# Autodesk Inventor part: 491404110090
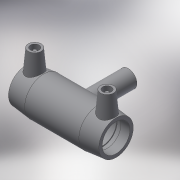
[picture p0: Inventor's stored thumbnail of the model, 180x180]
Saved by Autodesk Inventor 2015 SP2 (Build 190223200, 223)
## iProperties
Created: 2017-06
Part Number: 491404110090
Material: Generic
Description: PLASSON REDUCING TEE 110x90x110
Document SubType Name: Modeling
Designer: KIM
Mass: 57.3761 g
Surface Area: 241.06 cm^2
Volume: 57.3761 cm^3
Density: 1 g/cm^3
Appearance: Default
Author: KIM
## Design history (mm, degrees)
derived "491404.ipt"
feature "Solid1::491404.ipt"
tag "TaggingFeature1"
body "Solid1"
other parameters: "d0" = 326, "d2" = 143, "d3" = 71, "d4" = 65.2, "d5" = 128.7, "d6" = 104.5, "d8" = 168 deg, "d10" = 28.4, "d11" = 9.46667, "d13" = 326, "d14" = 17.6296, "d17" = 99, "d19" = 3.52592, "d20" = 168 deg, "d22" = 132.99, "d23" = 143, "d25" = 135 deg, "d26" = 228.2, "d29" = 81, "d30" = 15, "d31" = 130.4, "d34" = 5 deg, "d35" = 15, "d39" = 5 deg, "d41" = 4, "d42" = 14, "d43" = 0, "d45" = 4, "d46" = 6, "d47" = 0, "d48" = -147, "d51" = 0, "d52" = 72, "d54" = 0, "d55" = 128.7, "d56" = 143, "d57" = 114.1, "d58" = 135 deg, "d59" = 71, "d60" = 71, "d61" = 135 deg, "d62" = 147, "d72" = 148.33, "d73" = 74.165, "d74" = -147, "d75" = 94.5, "d77" = 0, "d78" = 72, "d80" = 0, "d82" = 75.5, "d83" = 0, "d84" = 3, "d85" = 0, "d86" = 23.66667, "d87" = 130.3302, "d88" = 9.46667, "d89" = 3, "d90" = 0, "L_" = 326, "L_1" = 71, "D_" = 143, "A_" = 81, "d_2" = 12, "H_" = 147
